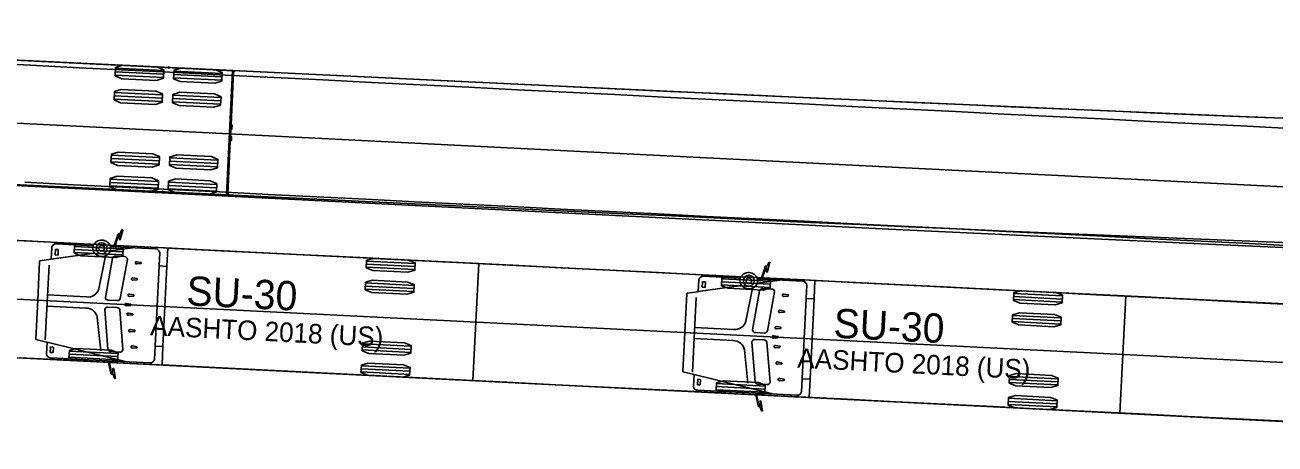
# Model space of a CAD drawing. Extents: x 260275 to 261282, y 610916 to 614143.
# Drawn here: x 260828.3 to 260913.8, y 612585.3 to 612613.9 of the extents above; entities that cross this region are included whole.
import ezdxf

# ---------------------------------------------------------------- set-up
doc = ezdxf.new("R2010")
doc.units = 0
doc.layers.add('TopoDOT_Transients', color=7, linetype='Continuous')

msp = doc.modelspace()

# ---------------------------------------------------------------- linework, layer by layer
at = {"layer": 'TopoDOT_Transients'}
for p, q in [((260834.438, 612610.46), (260837.734, 612610.301)), ((260834.449, 612610.689), (260837.745, 612610.53)), ((260834.46, 612610.918), (260837.756, 612610.758)), ((260838.433, 612610.267), (260841.729, 612610.107)), ((260838.444, 612610.496), (260841.74, 612610.336)), ((260838.455, 612610.725), (260841.751, 612610.565)), ((260842.47, 612610.76), (260842.06, 612602.27)), ((260950.706, 612601.011), (260777.483, 612609.681)), ((260834.358, 612608.812), (260837.654, 612608.653)), ((260834.369, 612609.041), (260837.665, 612608.881)), ((260834.38, 612609.27), (260837.676, 612609.11)), ((260838.353, 612608.619), (260841.649, 612608.459)), ((260838.364, 612608.848), (260841.66, 612608.688)), ((260838.375, 612609.077), (260841.672, 612608.917)), ((260842.323, 612606.252), (260842.348, 612606.775)), ((260842.361, 612607.042), (260842.348, 612606.777)), ((260842.335, 612606.511), (260842.265, 612606.515)), ((260842.323, 612606.246), (260842.31, 612605.981)), ((260834.151, 612604.534), (260837.447, 612604.374)), ((260834.162, 612604.763), (260837.458, 612604.603)), ((260834.173, 612604.991), (260837.469, 612604.832)), ((260838.146, 612604.34), (260841.442, 612604.181)), ((260838.157, 612604.569), (260841.453, 612604.41)), ((260838.168, 612604.798), (260841.465, 612604.639)), ((260834.071, 612602.886), (260837.367, 612602.726)), ((260834.082, 612603.115), (260837.378, 612602.955)), ((260834.093, 612603.343), (260837.389, 612603.184)), ((260838.066, 612602.692), (260841.363, 612602.533)), ((260838.078, 612602.921), (260841.374, 612602.762)), ((260838.089, 612603.15), (260841.385, 612602.991)), ((260833.021, 612598.292), (260830.055, 612597.874)), ((260830.351, 612598.549), (260830.332, 612598.171)), ((260830.545, 612598.539), (260830.351, 612598.549)), ((260832.93, 612598.796), (260830.411, 612598.922)), ((260830.526, 612598.161), (260830.545, 612598.539)), ((260831.635, 612598.335), (260834.964, 612598.168)), ((260831.646, 612598.543), (260834.975, 612598.376)), ((260831.656, 612598.751), (260834.985, 612598.584)), ((260835.629, 612598.661), (260834.095, 612598.444)), ((261025.504, 612585.252), (260776.884, 612597.696)), ((260829.911, 612597.465), (260829.656, 612592.366)), ((260830.332, 612598.171), (260830.526, 612598.161)), ((260833.31, 612595.855), (260833.771, 612598.11)), ((260834.254, 612597.942), (260833.768, 612595.269)), ((260835.079, 612598.053), (260834.463, 612598.084)), ((260834.786, 612595.188), (260835.272, 612597.861)), ((260836.211, 612597.572), (260835.91, 612597.551)), ((260835.918, 612597.705), (260836.215, 612597.654)), ((260836.215, 612597.654), (260836.211, 612597.572)), ((260837.445, 612597.414), (260837.17, 612591.929)), ((260837.976, 612597.388), (260837.701, 612591.903)), ((260851.621, 612597.543), (260854.95, 612597.376)), ((260851.631, 612597.751), (260854.96, 612597.584)), ((260835.652, 612596.6), (260835.949, 612596.549)), ((260835.949, 612596.549), (260835.945, 612596.466)), ((260851.61, 612597.335), (260854.939, 612597.168)), ((260877.197, 612596.58), (260874.678, 612596.707)), ((260875.923, 612596.536), (260879.252, 612596.369)), ((260835.945, 612596.466), (260835.644, 612596.445)), ((260851.535, 612595.837), (260854.864, 612595.67)), ((260851.546, 612596.045), (260854.875, 612595.878)), ((260851.556, 612596.253), (260854.885, 612596.086)), ((260877.287, 612596.077), (260874.321, 612595.659)), ((260874.617, 612596.334), (260874.598, 612595.956)), ((260874.598, 612595.956), (260874.792, 612595.946)), ((260874.811, 612596.324), (260874.617, 612596.334)), ((260874.792, 612595.946), (260874.811, 612596.324)), ((260875.902, 612596.119), (260879.231, 612595.953)), ((260875.912, 612596.327), (260879.241, 612596.161)), ((260877.576, 612593.639), (260878.037, 612595.895)), ((260878.52, 612595.726), (260878.034, 612593.053)), ((260879.896, 612596.444), (260878.362, 612596.228)), ((260879.346, 612595.837), (260878.73, 612595.868)), ((260829.81, 612595.431), (260832.474, 612595.297)), ((260833.961, 612595.077), (260834.577, 612595.047)), ((260835.213, 612594.854), (260835.511, 612594.803)), ((260835.707, 612595.36), (260835.406, 612595.339)), ((260835.414, 612595.493), (260835.711, 612595.442)), ((260835.511, 612594.803), (260835.507, 612594.721)), ((260835.711, 612595.442), (260835.707, 612595.36)), ((260874.178, 612595.25), (260873.921, 612590.151)), ((260879.052, 612592.972), (260879.538, 612595.645)), ((260880.478, 612595.355), (260880.176, 612595.334)), ((260880.184, 612595.489), (260880.482, 612595.438)), ((260880.482, 612595.438), (260880.478, 612595.355)), ((260881.711, 612595.198), (260881.435, 612589.713)), ((260882.242, 612595.171), (260881.966, 612589.686)), ((260895.876, 612595.114), (260899.206, 612594.947)), ((260895.887, 612595.322), (260899.216, 612595.155)), ((260895.897, 612595.53), (260899.227, 612595.363)), ((260829.771, 612594.666), (260832.436, 612594.532)), ((260833.943, 612591.723), (260833.726, 612594.431)), ((260833.937, 612594.603), (260834.553, 612594.572)), ((260834.747, 612594.41), (260834.963, 612591.702)), ((260835.507, 612594.721), (260835.206, 612594.7)), ((260835.642, 612594.065), (260835.341, 612594.044)), ((260835.349, 612594.198), (260835.647, 612594.147)), ((260835.647, 612594.147), (260835.642, 612594.065)), ((260880.211, 612594.25), (260879.91, 612594.229)), ((260879.918, 612594.383), (260880.216, 612594.332)), ((260880.216, 612594.332), (260880.211, 612594.25)), ((260895.822, 612594.032), (260899.151, 612593.865)), ((260833.212, 612593.894), (260833.444, 612591.616)), ((260874.075, 612593.216), (260876.74, 612593.082)), ((260879.973, 612593.143), (260879.672, 612593.123)), ((260879.68, 612593.277), (260879.977, 612593.226)), ((260879.977, 612593.226), (260879.973, 612593.143)), ((260895.801, 612593.616), (260899.13, 612593.449)), ((260895.812, 612593.824), (260899.141, 612593.657)), ((260835.769, 612592.94), (260835.454, 612592.919)), ((260835.461, 612593.073), (260835.773, 612593.022)), ((260835.773, 612593.022), (260835.769, 612592.94)), ((260874.037, 612592.451), (260876.702, 612592.317)), ((260878.203, 612592.387), (260878.818, 612592.356)), ((260878.226, 612592.862), (260878.842, 612592.831)), ((260879.772, 612592.504), (260879.471, 612592.484)), ((260879.479, 612592.638), (260879.777, 612592.587)), ((260879.777, 612592.587), (260879.772, 612592.504)), ((260835.239, 612590.87), (260829.771, 612592.21)), ((260829.998, 612591.509), (260830.017, 612591.887)), ((260830.192, 612591.499), (260829.998, 612591.509)), ((260830.017, 612591.887), (260830.211, 612591.877)), ((260830.211, 612591.877), (260830.192, 612591.499)), ((260831.287, 612591.385), (260834.616, 612591.219)), ((260831.298, 612591.594), (260834.627, 612591.427)), ((260834.753, 612591.53), (260834.137, 612591.561)), ((260835.923, 612591.814), (260835.622, 612591.793)), ((260835.629, 612591.947), (260835.927, 612591.896)), ((260835.927, 612591.896), (260835.923, 612591.814)), ((260851.327, 612591.675), (260854.656, 612591.508)), ((260851.337, 612591.883), (260854.666, 612591.716)), ((260851.348, 612592.091), (260854.677, 612591.924)), ((260877.478, 612591.679), (260877.708, 612589.4)), ((260878.207, 612589.507), (260877.992, 612592.215)), ((260879.013, 612592.194), (260879.228, 612589.485)), ((260879.908, 612591.849), (260879.607, 612591.828)), ((260879.614, 612591.982), (260879.912, 612591.931)), ((260879.912, 612591.931), (260879.908, 612591.849)), ((260831.277, 612591.177), (260834.606, 612591.011)), ((260851.273, 612590.593), (260854.602, 612590.426)), ((260880.034, 612590.724), (260879.719, 612590.703)), ((260879.727, 612590.857), (260880.038, 612590.806)), ((260880.038, 612590.806), (260880.034, 612590.724)), ((260851.252, 612590.177), (260854.581, 612590.01)), ((260851.262, 612590.385), (260854.591, 612590.218)), ((260879.504, 612588.654), (260874.036, 612589.996)), ((260874.263, 612589.294), (260874.282, 612589.672)), ((260874.282, 612589.672), (260874.476, 612589.663)), ((260879.894, 612589.731), (260880.192, 612589.68)), ((260880.192, 612589.68), (260880.188, 612589.597)), ((260895.613, 612589.871), (260898.942, 612589.703)), ((260874.457, 612589.284), (260874.263, 612589.294)), ((260874.476, 612589.663), (260874.457, 612589.284)), ((260875.542, 612588.962), (260878.871, 612588.795)), ((260875.552, 612589.17), (260878.881, 612589.003)), ((260875.562, 612589.378), (260878.892, 612589.211)), ((260879.017, 612589.314), (260878.401, 612589.345)), ((260880.188, 612589.597), (260879.887, 612589.576)), ((260895.592, 612589.455), (260898.921, 612589.287)), ((260895.602, 612589.663), (260898.931, 612589.495)), ((260895.516, 612587.957), (260898.845, 612587.789)), ((260895.527, 612588.165), (260898.856, 612587.997)), ((260895.537, 612588.373), (260898.866, 612588.205))]:
    msp.add_line(p, q, dxfattribs=at)
for points in [[(260919.365, 612598.455), (260908.692, 612598.918), (260887.354, 612599.929), (260794.257, 612604.583), (260794.126, 612604.843), (260773.289, 612605.886), (260773.688, 612613.876), (260794.522, 612612.834), (260794.667, 612613.073), (260858.102, 612610.013), (260879.417, 612609.02), (260900.73, 612608.077), (260911.385, 612607.632), (260922.039, 612607.21)], [(260842.54, 612610.734), (260842.541, 612610.756), (260794.667, 612613.073), (260794.462, 612608.828), (260794.257, 612604.583), (260842.13, 612602.266), (260842.131, 612602.289)], [(260915.204, 612606.792), (260911.882, 612606.959), (260908.558, 612607.125), (260905.234, 612607.292), (260901.908, 612607.458), (260898.581, 612607.625), (260895.254, 612607.791), (260891.926, 612607.958), (260888.598, 612608.125), (260885.269, 612608.291), (260881.94, 612608.458), (260878.61, 612608.625), (260875.28, 612608.791), (260871.95, 612608.958), (260868.62, 612609.125), (260865.29, 612609.291), (260861.959, 612609.458), (260858.628, 612609.625), (260855.298, 612609.791), (260851.967, 612609.958), (260848.636, 612610.125), (260845.305, 612610.292), (260841.974, 612610.458), (260838.643, 612610.625), (260835.312, 612610.792), (260831.981, 612610.958), (260828.65, 612611.125), (260825.319, 612611.292)], [(260915.714, 612607.457), (260912.384, 612607.591), (260909.055, 612607.727), (260905.725, 612607.865), (260902.395, 612608.006), (260899.065, 612608.148), (260895.735, 612608.292), (260892.405, 612608.438), (260889.075, 612608.585), (260885.745, 612608.734), (260882.415, 612608.884), (260879.084, 612609.036), (260875.754, 612609.188), (260872.423, 612609.342), (260869.093, 612609.496), (260865.762, 612609.652), (260862.431, 612609.808), (260859.101, 612609.965), (260855.77, 612610.123), (260852.439, 612610.282), (260849.108, 612610.441), (260845.778, 612610.601), (260842.447, 612610.761), (260839.116, 612610.922), (260838.117, 612610.97)], [(260842.419, 612606.771), (260842.432, 612607.037), (260842.431, 612607.039), (260842.361, 612607.042), (260842.363, 612607.078), (260842.539, 612610.709), (260842.539, 612610.71)], [(260842.132, 612602.313), (260842.132, 612602.314), (260842.308, 612605.945), (260842.31, 612605.981), (260842.38, 612605.977), (260842.38, 612605.979), (260842.393, 612606.245)], [(260914.921, 612598.798), (260911.58, 612598.965), (260908.241, 612599.132), (260904.904, 612599.299), (260901.567, 612599.466), (260898.231, 612599.633), (260894.896, 612599.8), (260891.562, 612599.966), (260888.228, 612600.133), (260884.894, 612600.3), (260881.561, 612600.467), (260878.228, 612600.634), (260874.895, 612600.801), (260871.563, 612600.967), (260868.231, 612601.134), (260864.899, 612601.301), (260861.567, 612601.468), (260858.235, 612601.634), (260854.903, 612601.801), (260851.572, 612601.968), (260848.24, 612602.135), (260844.909, 612602.301), (260841.577, 612602.468), (260838.246, 612602.635), (260834.914, 612602.802), (260831.583, 612602.968), (260828.252, 612603.135)], [(260935.769, 612585.699), (260893.177, 612587.866), (260772.689, 612593.901), (260773.089, 612601.891), (260900.569, 612595.515), (260943.182, 612593.414)], [(260915.376, 612598.964), (260912.04, 612599.098), (260908.705, 612599.234), (260905.37, 612599.373), (260902.035, 612599.513), (260898.7, 612599.656), (260895.366, 612599.8), (260892.032, 612599.946), (260888.698, 612600.094), (260885.364, 612600.243), (260882.03, 612600.393), (260878.697, 612600.544), (260875.364, 612600.697), (260872.03, 612600.851), (260868.697, 612601.006), (260865.365, 612601.161), (260862.032, 612601.318), (260858.699, 612601.475), (260855.367, 612601.633), (260852.034, 612601.792), (260848.702, 612601.951), (260845.37, 612602.111), (260842.038, 612602.271), (260838.705, 612602.432), (260837.706, 612602.48)], [(260914.879, 612594.794), (260911.55, 612594.961), (260908.221, 612595.128), (260904.892, 612595.294), (260901.563, 612595.461), (260898.234, 612595.627), (260894.906, 612595.794), (260891.577, 612595.961), (260888.249, 612596.127), (260884.92, 612596.294), (260881.592, 612596.46), (260878.263, 612596.627), (260874.935, 612596.794), (260871.606, 612596.96), (260868.278, 612597.127), (260864.95, 612597.293), (260861.621, 612597.46), (260858.293, 612597.627), (260854.965, 612597.793), (260851.637, 612597.96), (260848.308, 612598.126), (260844.98, 612598.293), (260841.652, 612598.459), (260838.323, 612598.626), (260834.995, 612598.793), (260831.667, 612598.959), (260828.339, 612599.126), (260825.01, 612599.292)], [(260914.881, 612594.78), (260911.552, 612594.949), (260908.223, 612595.118), (260904.895, 612595.286), (260901.567, 612595.453), (260898.238, 612595.621), (260894.91, 612595.789), (260891.581, 612595.956), (260888.253, 612596.123), (260884.925, 612596.29), (260881.596, 612596.457), (260878.268, 612596.624), (260874.94, 612596.791), (260871.612, 612596.958), (260868.283, 612597.125), (260864.955, 612597.292), (260861.627, 612597.459), (260858.298, 612597.625), (260854.97, 612597.792), (260851.642, 612597.959), (260848.314, 612598.125), (260844.985, 612598.292), (260841.657, 612598.459), (260838.329, 612598.625), (260835.001, 612598.792), (260831.672, 612598.959), (260828.344, 612599.125), (260825.016, 612599.292)], [(260834.619, 612599.552), (260834.619, 612599.551), (260834.351, 612598.731), (260834.339, 612598.725), (260834.111, 612598.737)], [(260837.188, 612598.583), (260834.417, 612598.721), (260834.405, 612598.727), (260834.665, 612599.532), (260834.666, 612599.532)], [(260834.686, 612599.542), (260834.73, 612599.541), (260834.731, 612599.54), (260834.724, 612599.223), (260834.724, 612599.22), (260834.779, 612599.218), (260834.78, 612599.221), (260834.952, 612599.869), (260834.953, 612599.872), (260834.888, 612599.875), (260834.742, 612599.587), (260834.741, 612599.587), (260834.694, 612599.588)], [(260830.096, 612598.684), (260830.055, 612597.877), (260830.05, 612597.873), (260829.272, 612597.763), (260829.268, 612597.721), (260829.136, 612595.081), (260829.004, 612592.441), (260829.004, 612592.398), (260829.767, 612592.211), (260829.771, 612592.207), (260829.731, 612591.4)], [(260837.125, 612591.031), (260837.17, 612591.926), (260837.174, 612591.929), (260837.7, 612591.903), (260837.701, 612591.892), (260837.638, 612590.65), (260858.898, 612589.585), (260859.098, 612593.58), (260859.299, 612597.575), (260838.039, 612598.64), (260837.976, 612597.399), (260837.975, 612597.388), (260837.449, 612597.414), (260837.445, 612597.417), (260837.49, 612598.312)], [(260878.953, 612597.326), (260878.997, 612597.325), (260878.998, 612597.324), (260878.99, 612597.007), (260878.99, 612597.004), (260879.046, 612597.002), (260879.047, 612597.005), (260879.219, 612597.653), (260879.22, 612597.655), (260879.155, 612597.659), (260879.008, 612597.371), (260879.008, 612597.371), (260878.961, 612597.372)], [(260878.886, 612597.336), (260878.886, 612597.335), (260878.618, 612596.516), (260878.606, 612596.509), (260878.378, 612596.521)], [(260881.454, 612596.366), (260878.684, 612596.505), (260878.672, 612596.511), (260878.932, 612597.316), (260878.932, 612597.316)], [(260874.362, 612596.469), (260874.322, 612595.663), (260874.317, 612595.658), (260873.539, 612595.549), (260873.535, 612595.507), (260873.402, 612592.866), (260873.269, 612590.226), (260873.269, 612590.184), (260874.032, 612589.997), (260874.036, 612589.992), (260873.996, 612589.185)], [(260881.39, 612588.814), (260881.435, 612589.709), (260881.439, 612589.712), (260881.965, 612589.686), (260881.966, 612589.675), (260881.903, 612588.433), (260903.163, 612587.363), (260903.364, 612591.358), (260903.565, 612595.353), (260882.305, 612596.423), (260882.243, 612595.182), (260882.241, 612595.171), (260881.715, 612595.197), (260881.711, 612595.201), (260881.756, 612596.096)], [(260914.467, 612586.805), (260911.14, 612586.971), (260907.812, 612587.138), (260904.485, 612587.304), (260901.157, 612587.471), (260897.829, 612587.638), (260894.501, 612587.804), (260891.174, 612587.971), (260887.846, 612588.137), (260884.518, 612588.304), (260881.189, 612588.47), (260877.861, 612588.637), (260874.533, 612588.804), (260871.205, 612588.97), (260867.877, 612589.137), (260864.549, 612589.303), (260861.221, 612589.47), (260857.893, 612589.637), (260854.564, 612589.803), (260851.236, 612589.97), (260847.908, 612590.136), (260844.58, 612590.303), (260841.251, 612590.469), (260837.923, 612590.636), (260834.595, 612590.803), (260831.267, 612590.969), (260827.939, 612591.136)], [(260914.475, 612586.791), (260911.147, 612586.959), (260907.82, 612587.128), (260904.492, 612587.296), (260901.164, 612587.464), (260897.836, 612587.631), (260894.508, 612587.799), (260891.18, 612587.966), (260887.852, 612588.133), (260884.524, 612588.3), (260881.195, 612588.468), (260877.867, 612588.635), (260874.539, 612588.801), (260871.211, 612588.968), (260867.883, 612589.135), (260864.555, 612589.302), (260861.226, 612589.469), (260857.898, 612589.635), (260854.57, 612589.802), (260851.242, 612589.969), (260847.914, 612590.136), (260844.585, 612590.302), (260841.257, 612590.469), (260837.929, 612590.635), (260834.601, 612590.802), (260831.272, 612590.969), (260827.944, 612591.135)], [(260830.021, 612591.132), (260833.949, 612590.935), (260833.96, 612590.928), (260834.145, 612590.086), (260834.145, 612590.085)], [(260834.193, 612590.1), (260834.193, 612590.1), (260834.015, 612590.927), (260834.027, 612590.931), (260836.797, 612590.792)], [(260834.216, 612590.041), (260834.263, 612590.038), (260834.263, 612590.038), (260834.38, 612589.737), (260834.445, 612589.733), (260834.445, 612589.736), (260834.339, 612590.398), (260834.338, 612590.401), (260834.282, 612590.404), (260834.282, 612590.402), (260834.257, 612590.085), (260834.257, 612590.085), (260834.213, 612590.087)], [(260874.285, 612588.917), (260878.214, 612588.719), (260878.225, 612588.712), (260878.409, 612587.87), (260878.409, 612587.869)], [(260878.458, 612587.884), (260878.457, 612587.884), (260878.279, 612588.711), (260878.291, 612588.715), (260881.062, 612588.576)], [(260878.48, 612587.825), (260878.527, 612587.822), (260878.528, 612587.822), (260878.644, 612587.521), (260878.709, 612587.517), (260878.709, 612587.52), (260878.603, 612588.182), (260878.602, 612588.185), (260878.547, 612588.188), (260878.546, 612588.186), (260878.522, 612587.869), (260878.521, 612587.869), (260878.477, 612587.871)]]:
    msp.add_lwpolyline(points, dxfattribs=at)
for points in [[(260834.435, 612610.403), (260834.463, 612610.975), (260834.932, 612611.124), (260837.306, 612611.01), (260837.759, 612610.815), (260837.731, 612610.244), (260837.261, 612610.094), (260834.888, 612610.209)], [(260838.43, 612610.21), (260838.458, 612610.781), (260838.928, 612610.931), (260841.301, 612610.816), (260841.754, 612610.622), (260841.726, 612610.051), (260841.257, 612609.901), (260838.883, 612610.016)], [(260834.355, 612608.755), (260834.383, 612609.327), (260834.853, 612609.476), (260837.226, 612609.362), (260837.679, 612609.167), (260837.651, 612608.596), (260837.182, 612608.446), (260834.808, 612608.561)], [(260838.35, 612608.562), (260838.378, 612609.133), (260838.848, 612609.283), (260841.221, 612609.168), (260841.674, 612608.974), (260841.647, 612608.402), (260841.177, 612608.253), (260838.804, 612608.367)], [(260834.148, 612604.477), (260834.176, 612605.048), (260834.646, 612605.198), (260837.019, 612605.083), (260837.472, 612604.889), (260837.444, 612604.317), (260836.975, 612604.168), (260834.601, 612604.282)], [(260838.143, 612604.284), (260838.171, 612604.855), (260838.641, 612605.005), (260841.014, 612604.89), (260841.467, 612604.695), (260841.44, 612604.124), (260840.97, 612603.974), (260838.597, 612604.089)], [(260834.068, 612602.829), (260834.096, 612603.4), (260834.566, 612603.55), (260836.939, 612603.435), (260837.392, 612603.241), (260837.365, 612602.669), (260836.895, 612602.52), (260834.522, 612602.634)], [(260838.064, 612602.636), (260838.091, 612603.207), (260838.561, 612603.357), (260840.934, 612603.242), (260841.388, 612603.047), (260841.36, 612602.476), (260840.89, 612602.326), (260838.517, 612602.441)], [(260831.633, 612598.283), (260831.659, 612598.803), (260832.133, 612598.936), (260834.53, 612598.816), (260834.988, 612598.636), (260834.962, 612598.117), (260834.488, 612597.984), (260832.091, 612598.104)], [(260851.608, 612597.283), (260851.634, 612597.802), (260852.108, 612597.935), (260854.505, 612597.815), (260854.963, 612597.636), (260854.937, 612597.116), (260854.463, 612596.983), (260852.066, 612597.103)], [(260875.899, 612596.068), (260875.925, 612596.587), (260876.399, 612596.72), (260878.796, 612596.6), (260879.254, 612596.42), (260879.228, 612595.901), (260878.754, 612595.768), (260876.357, 612595.888)], [(260851.533, 612595.785), (260851.559, 612596.304), (260852.032, 612596.437), (260854.429, 612596.317), (260854.888, 612596.138), (260854.862, 612595.618), (260854.388, 612595.485), (260851.991, 612595.605)], [(260895.874, 612595.063), (260895.9, 612595.582), (260896.374, 612595.715), (260898.771, 612595.594), (260899.229, 612595.414), (260899.203, 612594.895), (260898.729, 612594.762), (260896.332, 612594.883)], [(260895.798, 612593.565), (260895.825, 612594.084), (260896.299, 612594.217), (260898.696, 612594.096), (260899.154, 612593.916), (260899.128, 612593.397), (260898.654, 612593.264), (260896.257, 612593.385)], [(260851.324, 612591.623), (260851.35, 612592.143), (260851.824, 612592.276), (260854.221, 612592.156), (260854.679, 612591.976), (260854.653, 612591.457), (260854.179, 612591.324), (260851.782, 612591.444)], [(260831.274, 612591.126), (260831.3, 612591.645), (260831.774, 612591.778), (260834.171, 612591.658), (260834.629, 612591.478), (260834.603, 612590.959), (260834.129, 612590.826), (260831.732, 612590.946)], [(260851.249, 612590.125), (260851.275, 612590.645), (260851.749, 612590.778), (260854.146, 612590.658), (260854.604, 612590.478), (260854.578, 612589.959), (260854.104, 612589.825), (260851.707, 612589.946)], [(260895.589, 612589.403), (260895.615, 612589.923), (260896.089, 612590.056), (260898.486, 612589.935), (260898.944, 612589.755), (260898.918, 612589.236), (260898.444, 612589.103), (260896.047, 612589.223)], [(260875.539, 612588.91), (260875.565, 612589.43), (260876.039, 612589.563), (260878.436, 612589.443), (260878.894, 612589.263), (260878.868, 612588.744), (260878.394, 612588.61), (260875.997, 612588.73)], [(260895.514, 612587.905), (260895.54, 612588.424), (260896.014, 612588.557), (260898.411, 612588.437), (260898.869, 612588.257), (260898.843, 612587.737), (260898.369, 612587.604), (260895.972, 612587.725)]]:
    msp.add_lwpolyline(points, close=True, dxfattribs=at)
for centre, radius in [((260838.117, 612610.97), 0.0417), ((260842.573, 612610.72), 0.0266), ((260837.706, 612602.48), 0.0417), ((260842.166, 612602.299), 0.0266), ((260833.513, 612598.621), 0.374), ((260833.513, 612598.621), 0.193), ((260877.78, 612596.406), 0.374), ((260877.78, 612596.406), 0.193)]:
    msp.add_circle(centre, radius, dxfattribs=at)
for centre, radius, start, end in [((260842.573, 612610.72), 0.0363, 196.99056, 158.15319), ((260842.383, 612606.773), 0.0354, 1.52153, 173.707), ((260842.383, 612606.773), 0.0352, 176.62793, 357.21442), ((260842.358, 612606.246), 0.0352, 357.24558, 177.83207), ((260842.358, 612606.246), 0.0352, 177.01753, 359.65693), ((260842.166, 612602.299), 0.0363, 196.3068, 157.46943), ((260833.51, 612598.554), 0.628, 16.88607, 157.37776), ((260834.657, 612599.569), 0.0418, 27.62592, 204.64085), ((260834.657, 612599.575), 0.0434, 281.04629, 311.71906), ((260830.374, 612598.643), 0.282, 82.50494, 171.58436), ((260833.427, 612598.625), 0.526, 161.07794, 219.32394), ((260833.509, 612598.69), 0.629, 219.17835, 267.86765), ((260833.524, 612598.69), 0.63, 266.48757, 318.89038), ((260833.6, 612598.617), 0.524, 319.39178, 13.19186), ((260837.171, 612598.26), 0.323, 9.28436, 87.13277), ((260834.44, 612597.892), 0.193, 83.07586, 164.99035), ((260835.088, 612597.869), 0.184, 357.72534, 92.5966), ((260835.895, 612597.617), 0.091, 75.44932, 169.6132), ((260835.896, 612597.641), 0.0909, 184.61668, 278.85188), ((260878.924, 612597.353), 0.0418, 27.61114, 204.62607), ((260835.629, 612596.512), 0.091, 75.44932, 169.6132), ((260835.63, 612596.535), 0.0909, 184.61668, 278.85188), ((260874.641, 612596.428), 0.282, 82.49016, 171.56958), ((260877.694, 612596.41), 0.526, 161.06316, 219.30916), ((260877.777, 612596.339), 0.628, 16.87129, 157.36298), ((260877.867, 612596.401), 0.524, 319.377, 13.17708), ((260878.924, 612597.359), 0.0434, 281.03151, 311.70428), ((260832.566, 612596.065), 0.773, 263.15814, 344.2423), ((260877.775, 612596.474), 0.629, 219.16357, 267.85287), ((260877.79, 612596.474), 0.63, 266.47279, 318.8756), ((260878.707, 612595.676), 0.193, 83.06108, 164.97557), ((260879.354, 612595.652), 0.184, 357.71056, 92.58182), ((260881.438, 612596.044), 0.323, 9.26958, 87.11799), ((260833.952, 612595.262), 0.184, 177.7309, 272.59104), ((260834.6, 612595.238), 0.193, 263.07093, 344.99528), ((260835.19, 612594.766), 0.091, 75.44932, 169.6132), ((260835.391, 612595.405), 0.091, 75.44932, 169.6132), ((260835.392, 612595.429), 0.0909, 184.61668, 278.85188), ((260880.161, 612595.401), 0.091, 75.43454, 169.59841), ((260880.162, 612595.424), 0.0909, 184.6019, 278.8371), ((260832.451, 612593.76), 0.773, 10.02323, 91.10739), ((260833.91, 612594.42), 0.184, 81.6745, 176.53463), ((260834.557, 612594.379), 0.193, 9.27026, 91.19461), ((260835.192, 612594.79), 0.091, 184.65234, 278.81621), ((260835.326, 612594.11), 0.0909, 75.41365, 169.64885), ((260835.327, 612594.134), 0.091, 184.65234, 278.81621), ((260879.895, 612594.295), 0.091, 75.43454, 169.59841), ((260879.896, 612594.319), 0.0909, 184.6019, 278.8371), ((260876.832, 612593.849), 0.773, 263.14336, 344.22752), ((260879.657, 612593.189), 0.091, 75.43454, 169.59841), ((260879.658, 612593.212), 0.0909, 184.6019, 278.8371), ((260835.452, 612592.985), 0.0909, 75.41365, 169.64885), ((260835.454, 612593.009), 0.091, 184.65234, 278.81621), ((260876.716, 612591.544), 0.773, 10.00845, 91.09261), ((260878.176, 612592.204), 0.184, 81.65971, 176.51985), ((260878.218, 612593.046), 0.184, 177.71612, 272.57626), ((260878.822, 612592.163), 0.193, 9.25547, 91.17983), ((260878.866, 612593.022), 0.193, 263.05615, 344.9805), ((260879.456, 612592.55), 0.091, 75.43454, 169.59841), ((260879.457, 612592.574), 0.091, 184.63756, 278.80143), ((260830.012, 612591.413), 0.282, 182.68117, 271.7606), ((260834.133, 612591.754), 0.193, 189.27519, 271.18968), ((260834.779, 612591.713), 0.184, 261.66893, 356.54019), ((260835.607, 612591.859), 0.0909, 75.41365, 169.64885), ((260835.608, 612591.883), 0.091, 184.65234, 278.81621), ((260879.592, 612591.894), 0.0909, 75.39887, 169.63407), ((260879.593, 612591.918), 0.091, 184.63756, 278.80143), ((260836.814, 612591.115), 0.323, 267.13277, 344.98117), ((260879.717, 612590.769), 0.0909, 75.39887, 169.63407), ((260879.719, 612590.793), 0.091, 184.63756, 278.80143), ((260834.181, 612590.064), 0.0418, 149.62469, 326.63962), ((260834.181, 612590.058), 0.0434, 42.54647, 73.21925), ((260879.871, 612589.643), 0.0909, 75.39887, 169.63407), ((260874.277, 612589.199), 0.282, 182.66639, 271.74582), ((260878.398, 612589.538), 0.193, 189.2604, 271.1749), ((260879.044, 612589.497), 0.184, 261.65415, 356.52541), ((260879.873, 612589.666), 0.091, 184.63756, 278.80143), ((260881.078, 612588.898), 0.323, 267.11799, 344.96639), ((260878.445, 612587.848), 0.0418, 149.6099, 326.62484), ((260878.445, 612587.842), 0.0434, 42.53169, 73.20447)]:
    msp.add_arc(centre, radius, start, end, dxfattribs=at)

# ---------------------------------------------------------------- texts
for s, height, rotation, p in [('SU-30', 2, 357.13277, (260839.274, 612594.733)), ('AASHTO 2018 (US)', 1.33333, 357.13277, (260836.812, 612592.687)), ('SU-30', 2, 357.11799, (260883.54, 612592.516)), ('AASHTO 2018 (US)', 1.33333, 357.11799, (260881.077, 612590.471))]:
    msp.add_text(s, height=height, rotation=rotation, dxfattribs=at).set_placement(p)

doc.saveas('drawing.dxf')
